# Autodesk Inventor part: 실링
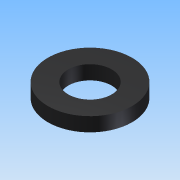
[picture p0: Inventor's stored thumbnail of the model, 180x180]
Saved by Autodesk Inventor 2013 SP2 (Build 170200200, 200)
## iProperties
Created: 2025-10
Part Number: 실링
Material: Generic
Document SubType Name: Modeling
Designer: 601
Density: 1 g/cm^3
Author: 601
변환 표준: STEP AP214IS
전처리기: Build: 200, Release: 2013 SP2 Update 6 - Date: Thu 07/17/2014
전송 단위: 밀리미터
불확실성: 0.01
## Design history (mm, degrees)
node "실링1"
node "솔리드1"
node "기준1"
